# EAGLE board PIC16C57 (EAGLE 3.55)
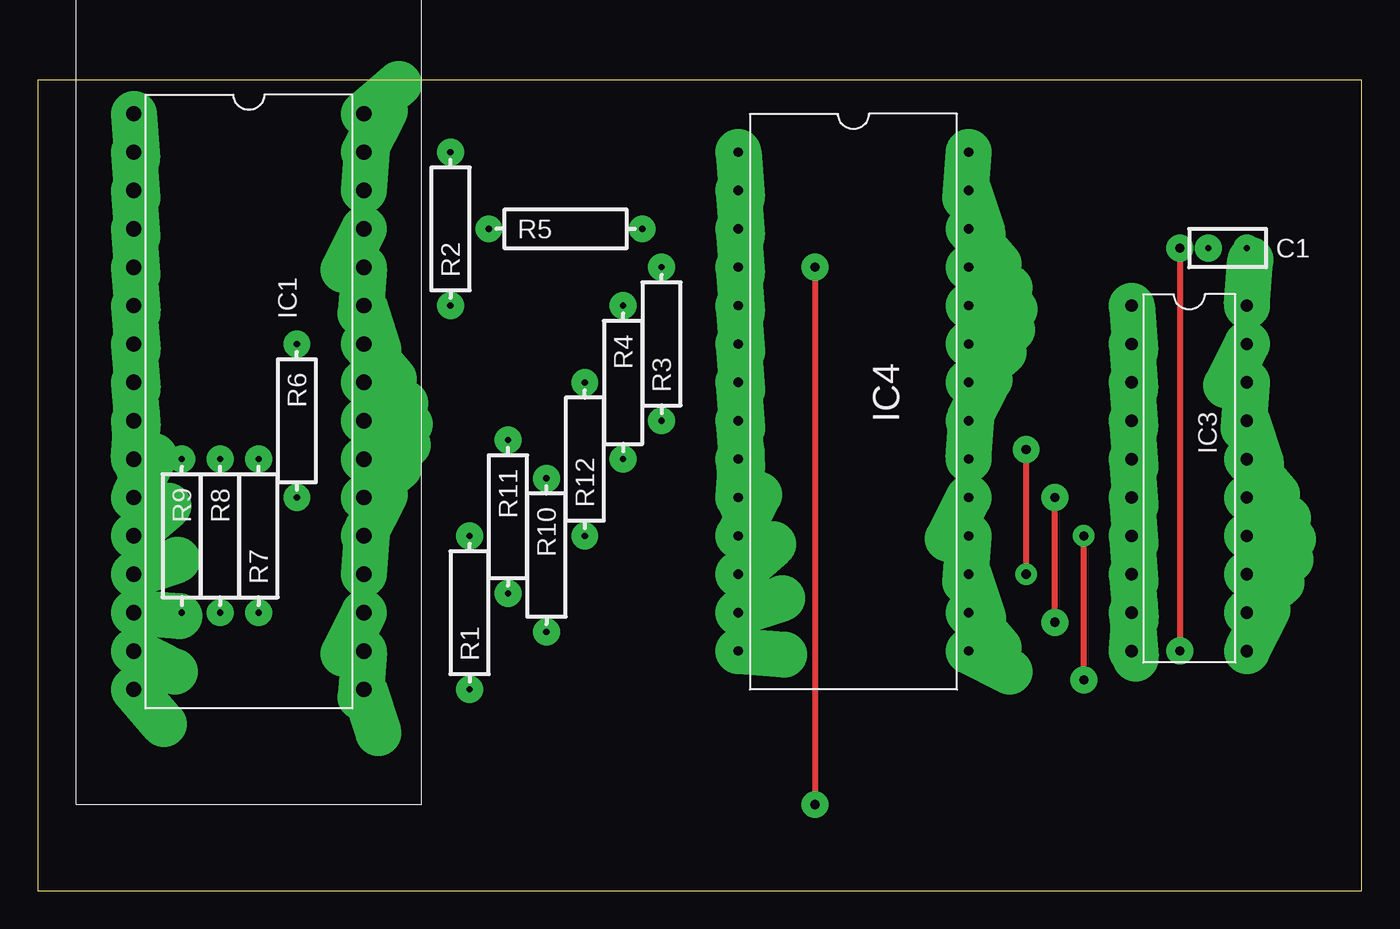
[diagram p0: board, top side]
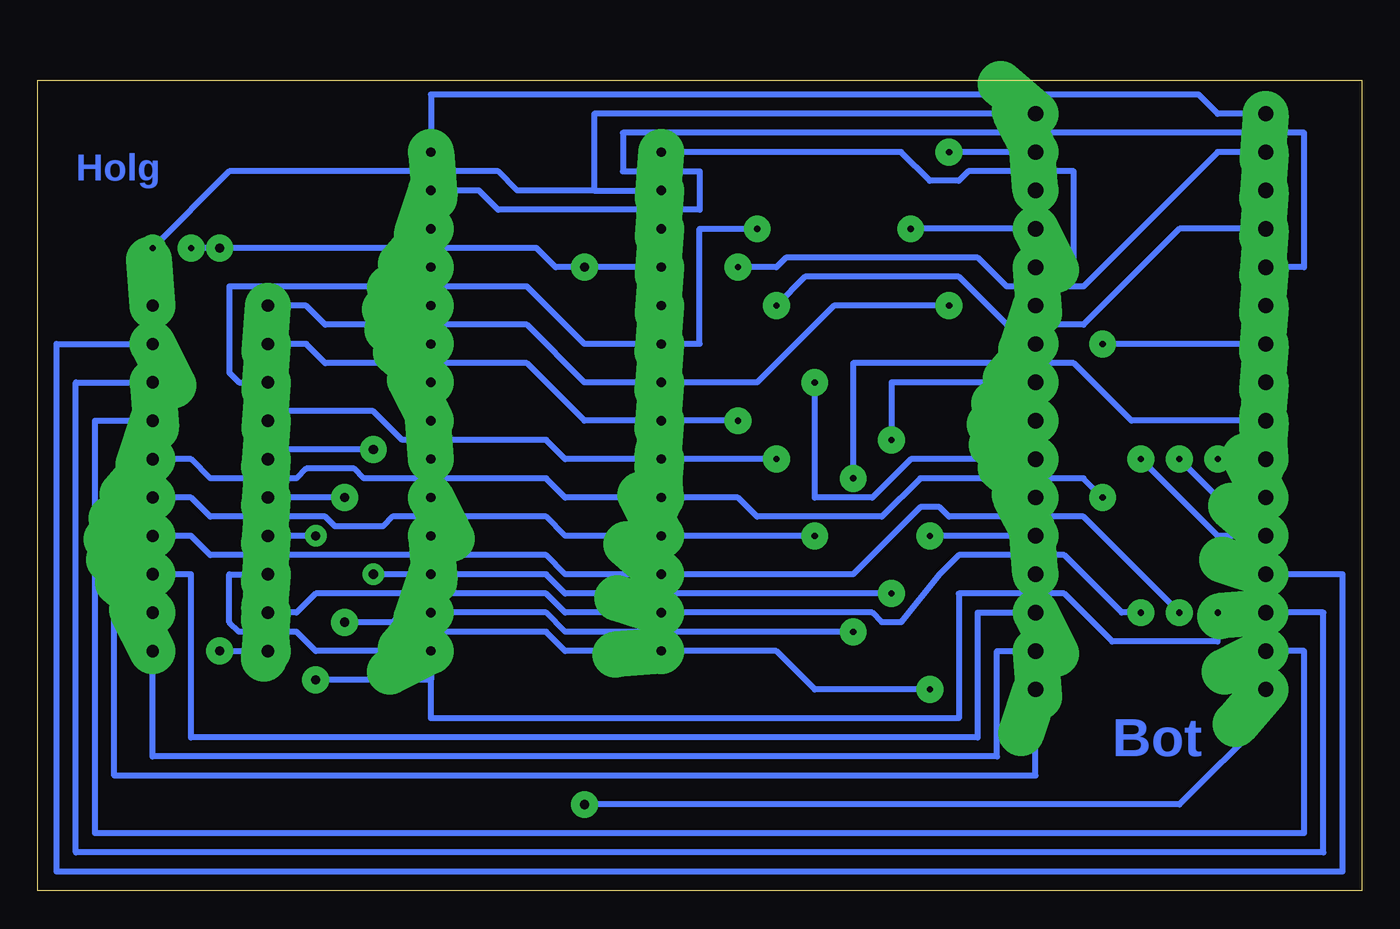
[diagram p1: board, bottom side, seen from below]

Size 87.61 x 53.65 mm. Coordinates in mm from the lower left corner, seen from the top.
Outline: 0,0 87.61,0 87.61,53.65 0,53.65 0,0
Copper layers used: Top, Bottom

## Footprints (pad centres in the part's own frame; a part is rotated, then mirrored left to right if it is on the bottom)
RM2,5 = drill 0.406 pad 1.778 round:  -1.27,0;  1.27,0
XTO_32 = drill 1.016 pad 3.048 offset:  0,0;  2.54,0;  15.24,0;  17.78,0;  5.08,0;  7.62,0;  12.7,0;  10.16,0;  20.32,0;  22.86,0;  25.4,0;  27.94,0;  30.48,0;  33.02,0;  35.56,0;  38.1,0;  38.1,15.24;  35.56,15.24;  33.02,15.24;  30.48,15.24;  27.94,15.24;  25.4,15.24;  22.86,15.24;  20.32,15.24;  17.78,15.24;  15.24,15.24;  12.7,15.24;  10.16,15.24;  7.62,15.24;  5.08,15.24;  2.54,15.24;  0,15.24
L-20B = drill 0.813 pad 3.048 offset:  0,0;  2.54,0;  5.08,0;  7.62,0;  10.16,0;  12.7,0;  15.24,0;  17.78,0;  20.32,0;  22.86,0;  22.86,7.62;  20.32,7.62;  17.78,7.62;  15.24,7.62;  12.7,7.62;  10.16,7.62;  7.62,7.62;  5.08,7.62;  2.54,7.62;  0,7.62
L-28B = drill 0.61 pad 3.048 offset:  -16.51,-7.62;  -13.97,-7.62;  -1.27,-7.62;  1.27,-7.62;  -11.43,-7.62;  -8.89,-7.62;  -3.81,-7.62;  -6.35,-7.62;  3.81,-7.62;  6.35,-7.62;  8.89,-7.62;  11.43,-7.62;  13.97,-7.62;  16.51,-7.62;  16.51,7.62;  13.97,7.62;  11.43,7.62;  8.89,7.62;  6.35,7.62;  3.81,7.62;  1.27,7.62;  -1.27,7.62;  -3.81,7.62;  -6.35,7.62;  -8.89,7.62;  -11.43,7.62;  -13.97,7.62;  -16.51,7.62
S04 = drill 0.406 pad 1.778 round:  -5.08,0;  5.08,0

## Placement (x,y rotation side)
C1  C100NK  [RM2,5]  78.74,42.55 0 top
IC1  Sockel1  [XTO_32]  6.35,51.44 270 top
IC3  GAL16V8D-QP  [L-20B]  72.39,38.73 270 top
IC4  16C57P  [L-28B]  53.98,32.38 270 top
R1  4k7  [S04]  28.57,18.41 90 top
R2  4k7  [S04]  27.3,43.81 90 top
R3  4k7  [S04]  41.27,36.2 90 top
R4  4k7  [S04]  38.73,33.66 270 top
R5  4k7  [S04]  34.92,43.81 0 top
R6  4k7  [S04]  17.14,31.11 270 top
R7  4k7  [S04]  14.61,23.5 90 top
R8  4k7  [S04]  12.06,23.5 270 top
R9  4k7  [S04]  9.53,23.5 270 top
R10  4k7  [S04]  33.66,22.23 270 top
R11  4k7  [S04]  31.11,24.77 270 top
R12  4k7  [S04]  36.2,28.57 90 top

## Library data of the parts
C1 IC4 R1-R12 = holg_plt
IC1 IC3 = galeprom

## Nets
+5V: C1. IC1. IC3. IC4.
A0: IC3. IC4. R7.
A1: IC3. IC4. R8.
A2: IC3. IC4. R9.
A3: IC3. IC4. R10.
A5: IC3. IC4. R6.
A7: IC1. IC4.
A10: IC3. IC4. R12.
A11: IC3. IC4. R11.
A12: IC3. IC4. R4.
A13: IC1. IC4.
A14: IC3. IC4. R5.
A16: IC3. IC4. R3.
A18: IC3. IC4. R2.
D0: IC1. IC3.
D1: IC1. IC3.
D2: IC1. IC3.
D3: IC1. IC3.
D4: IC1. IC3.
D5: IC1. IC3.
D7: IC3. IC4. R1.
GND: C1. IC1. IC3. IC4.
N$1: IC1. R1.
N$2: IC1. R2.
N$3: IC1. R3.
N$4: IC1. R4.
N$5: IC1. R5.
N$6: IC1. R6.
N$7: IC1. R7.
N$8: IC1. R8.
N$9: IC1. R9.
N$10: IC1. R10.
N$11: IC1. R11.
N$12: IC1. R12.
VPP: IC1. IC4.

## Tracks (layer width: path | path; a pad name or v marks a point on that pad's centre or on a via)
+5V
  Bottom 0.406: IC1. 50.8,51.44 50.8,46.35 | 50.8,46.35 46.35,46.35 | 50.8,46.35 55.88,46.35 57.15,47.62 74.93,47.62 C1. IC3.
A0
  Bottom 0.406: 72.39,18.41 70.48,18.41 69.22,19.68 53.98,19.68 52.7,18.41 46.35,18.41 32.38,18.41 31.75,17.78 30.48,17.78 27.94,20.95 26.67,22.23 19.68,22.23 15.88,18.41 14.61,18.41
A1
  Bottom 0.406: 80.01,23.5 77.47,23.5 76.2,22.23 53.98,22.23 52.7,20.95 46.35,20.95 33.66,20.95 29.21,25.4 27.94,25.4 27.3,24.77 18.41,24.77 R8.
A2  (via drill 0.61 pad 1.42, 0.61 pad 1.78)
  Top 0.406: v69.22,13.97 v69.22,23.5
  Bottom 0.406: R9. 9.53,16.51 16.51,16.51 19.68,19.68 26.67,19.68 26.67,11.43 61.59,11.43 61.59,13.97 | v69.22,23.5 72.39,23.5 | 61.59,15.88 61.59,13.97 | 61.59,13.97 v69.22,13.97
A3  (via drill 0.61 pad 1.78)
  Top 0.406: v67.31,17.78 v67.31,26.04
  Bottom 0.406: R10. 52.7,17.14 53.98,18.41 61.59,18.41 63.5,18.41 64.14,17.78 v67.31,17.78 | v67.31,26.04 72.39,26.04
A5
  Bottom 0.406: 80.01,28.57 77.47,28.57 76.2,27.3 70.48,27.3 69.85,27.94 66.67,27.94 66.04,27.3 53.98,27.3 52.7,26.04 46.35,26.04 41.27,26.04 40.01,24.77 31.75,24.77 29.21,27.3 18.41,27.3 R6.
A7
  Bottom 0.406: 6.35,41.27 3.81,41.27 3.81,50.16 48.9,50.16 48.9,47.62 43.81,47.62 43.81,45.09 57.15,45.09 58.42,46.35 61.59,46.35
A10
  Bottom 0.406: 80.01,26.04 77.47,26.04 76.2,24.77 68.58,24.77 67.94,24.13 64.77,24.13 64.14,24.77 53.98,24.77 52.7,23.5 46.35,23.5 36.2,23.5
A11  (via drill 0.61 pad 1.42, 0.61 pad 1.78)
  Top 0.406: v65.41,20.95 v65.41,29.21
  Bottom 0.406: R11. 52.7,19.68 53.98,20.95 61.59,20.95 v65.41,20.95 | v65.41,29.21 71.75,29.21 72.39,28.57
A12
  Bottom 0.406: 72.39,31.11 71.75,31.75 65.41,31.75 63.5,29.84 53.98,29.84 52.7,28.57 46.35,28.57 R4.
A13
  Bottom 0.406: 46.35,48.9 30.48,48.9 28.57,46.99 26.67,46.99 26.04,47.62 19.05,47.62 19.05,41.27 21.59,41.27
A14
  Bottom 0.406: 43.81,36.2 51.44,36.2 55.24,40.01 74.93,40.01 74.93,34.29 74.3,33.66 72.39,33.66 | 43.81,36.2 46.35,36.2 | 43.81,36.2 43.81,43.81 R5.
A16
  Bottom 0.406: 72.39,36.2 69.85,36.2 68.58,34.92 55.24,34.92 51.44,31.11 46.35,31.11 41.27,31.11
A18
  Bottom 0.406: 72.39,38.73 69.85,38.73 68.58,37.47 55.24,37.47 51.44,33.66 46.35,33.66 40.01,33.66 34.92,38.73 27.3,38.73
D0
  Bottom 0.406: 6.35,20.95 1.27,20.95 1.27,1.27 86.36,1.27 86.36,36.2 80.01,36.2
D1
  Bottom 0.406: 6.35,18.41 2.54,18.41 2.54,2.54 85.09,2.54 85.09,33.66 80.01,33.66
D2
  Bottom 0.406: 6.35,15.88 3.81,15.88 3.81,3.81 83.82,3.81 83.82,31.11 80.01,31.11
D3
  Bottom 0.406: 21.59,13.34 21.59,7.62 82.55,7.62 82.55,18.41 80.01,18.41
D4
  Bottom 0.406: 21.59,15.88 24.13,15.88 24.13,8.89 80.01,8.89 80.01,15.88
D5
  Bottom 0.406: 21.59,18.41 25.4,18.41 25.4,10.16 77.47,10.16 77.47,20.95 80.01,20.95
D7
  Bottom 0.406: 72.39,20.95 74.93,20.95 74.93,17.78 74.3,17.14 70.48,17.14 69.22,15.88 64.77,15.88 63.5,17.14 53.98,17.14 52.7,15.88 46.35,15.88 38.73,15.88 36.2,13.34 28.57,13.34
GND  (via drill 0.61 pad 1.78)
  Top 0.406: v75.56,42.55 v75.56,15.88 | v51.44,41.27 v51.44,5.71
  Bottom 0.406: v75.56,15.88 72.39,15.88 | 77.47,42.55 v75.56,42.55 54.61,42.55 53.34,41.27 v51.44,41.27 46.35,41.27 | 6.35,13.34 6.35,11.43 12.06,5.71 v51.44,5.71
N$1
  Bottom 0.406: 21.59,23.5 R1.
N$2
  Bottom 0.406: 21.59,48.9 R2.
N$3
  Bottom 0.406: R3. 38.73,41.27 38.1,41.91 25.4,41.91 23.5,40.01 18.41,40.01 9.53,48.9 6.35,48.9
N$4
  Bottom 0.406: 38.73,38.73 36.83,40.64 26.67,40.64 23.5,37.47 18.41,37.47 12.06,43.81 6.35,43.81
N$5
  Bottom 0.406: 21.59,43.81 29.84,43.81
N$6
  Bottom 0.406: 6.35,36.2 17.14,36.2
N$7
  Bottom 0.406: 6.35,23.5 9.53,23.5 R7.
N$8
  Bottom 0.406: 6.35,26.04 9.53,26.04 12.06,28.57
N$9
  Bottom 0.406: 6.35,28.57 9.53,28.57
N$10
  Bottom 0.406: 6.35,31.11 15.24,31.11 19.05,34.92 33.66,34.92 33.66,27.3
N$11
  Bottom 0.406: 31.11,29.84 31.11,33.66 21.59,33.66
N$12
  Bottom 0.406: R12. 36.2,26.04 32.38,26.04 29.84,28.57 21.59,28.57
VPP
  Bottom 0.406: 6.35,51.44 9.53,51.44 10.79,52.7 61.59,52.7 IC4.

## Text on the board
Bottom: Holg | Bot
